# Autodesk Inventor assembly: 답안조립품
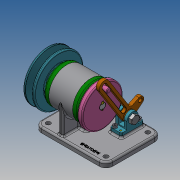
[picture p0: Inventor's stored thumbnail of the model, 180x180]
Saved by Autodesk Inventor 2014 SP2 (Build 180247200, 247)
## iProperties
Created: 2019-09
Part Number: 답안조립품
Document SubType Name: Assembly
Designer: kb542
Author: kb542
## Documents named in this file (19)
- C:\Users\kb542\Desktop\390904V1007\답안조립품.iam
- C:\Users\kb542\Desktop\390904V1007\본체.ipt
- C:\Users\kb542\Desktop\390904V1007\V-벨트풀리.ipt
- C:\Users\kb542\Desktop\390904V1007\너트 M8.ipt
- C:\Users\kb542\Desktop\390904V1007\너트 M10x1.ipt
- C:\Users\kb542\Desktop\390904V1007\돌림판.ipt
- C:\Users\kb542\Desktop\390904V1007\멈춤나사 M3x5.ipt
- C:\Users\kb542\Desktop\390904V1007\베어링 6004.ipt
- C:\Users\kb542\Desktop\390904V1007\볼트 M4.ipt
- C:\Users\kb542\Desktop\390904V1007\오일 실 17 30 5.ipt
- C:\Users\kb542\Desktop\390904V1007\와셔 8x15.5.ipt
- C:\Users\kb542\Desktop\390904V1007\축.ipt
- C:\Users\kb542\Desktop\390904V1007\커버.ipt
- C:\Users\kb542\Desktop\390904V1007\크랭크.ipt
- C:\Users\kb542\Desktop\390904V1007\키 4 x 4 x 8.ipt
- C:\Users\kb542\Desktop\390904V1007\키 5 x 5 x 12.ipt
- C:\Users\kb542\Desktop\390904V1007\핀 3 x 8.ipt
- C:\Users\kb542\Desktop\390904V1007\힌지 축.ipt
- C:\Users\kb542\Desktop\390904V1007\힌지.ipt
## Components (3 placed, 2 different names)
1. V-벨트풀리:1 — 각도:4
2. 핀 3 x 8:1
3. 핀 3 x 8:2
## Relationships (1: Angle 1)
- 각도:4 [Angle]: V-벨트풀리:1
